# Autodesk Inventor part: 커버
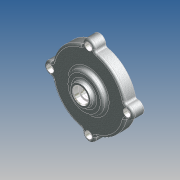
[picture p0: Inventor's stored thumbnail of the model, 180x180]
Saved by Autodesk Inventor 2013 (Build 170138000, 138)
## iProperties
Company: 한국ATC센터
Created: 2012-05
Part Number: 커버
Document SubType Name: 모델링
Designer: KYOUNG IL JANG
Mass: 196.657 g
Surface Area: 278.607 cm^2
Volume: 72.5671 cm^3
Density: 2.71 g/cm^3
Material: 알루미늄-6061
변환 표준: STEP AP214IS
파일 이름: C:\Users\SeoGD\Desktop\?쒗뿕\而ㅻ쾭-1.stp
전처리기: Build: 253, Release: 2010 SP1 - Date: Wed 07/29/2009
전송 단위: 밀리미터
불확실성: 0.01
Author: KYOUNG IL JANG
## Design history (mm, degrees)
sketch "스케치1"
  geometry: L1 (0, 0)-(0, 26); L2 (50, 0)-(50, 15); L3 (50, 15)-(25, 15); L4 (25, 15)-(25, 21); L5 (25, 21)-(15, 21); L6 (15, 21)-(13.66, 26); L7 (13.66, 26)-(10, 26); L8 (50, 0)-(45, 0); L9 (45, 0)-(45, 10); L10 (45, 10)-(14.5, 10); L11 (14.5, 10)-(13.266, 3); L12 (13.266, 3)-(11, 3); L13 (11, 3)-(11, 16); L14 (11, 16)-(7.5, 16); L15 (7.5, 16)-(7.5, 19); L16 (7.5, 19)-(10, 19); L17 (10, 19)-(10, 26)
  constraints: 34 end point, 10 parallel, 2 perpendicular, 2 point on line, 1 vertical
  dimensions: "d11" = 100 diameter of L2 L1; "d12" = 22 diameter of L13 L1; "d13" = 90 diameter of L9 L1; "d14" = 15 distance between parallel lines of L3 L8; "d15" = 10 distance between parallel lines of L8 L10; "d16" = 29 diameter of L10.end L1; "d17" = 100 deg angle of L11 L10; "d18" = 7 distance between parallel lines of L12 L10; "d19" = 13 distance between parallel lines of L14 L12; "d20" = 3 distance between parallel lines of L16 L14; "d21" = 15 diameter of L15 L1; "d22" = 20 diameter of L17 L1; "d23" = 30 diameter of L5.end L1; "d24" = 6 distance between parallel lines of L5 L3; "d25" = 50 diameter of L4 L1; "d26" = 105 deg angle of L5 L6; "d50" = 26 distance of L1.start L1.end
revolve "회전1" sketch "스케치1" stored, may be unused: angle "d27" = 90 deg
sketch "스케치2" dims "d29" = 104
  geometry: A1 r 8.5 centre (0, 52) between (8.074, 49.344) and (-8.074, 49.344); A2 r 50 centre (0, 0) between (-8.074, 49.344) and (8.074, 49.344) reference; 2 further points
  constraints: 4 point on circle, 2 vertical alignment, 1 centre point, 1 coincident, 2 other
  dimensions: "d28" = 17 diameter of A1
extrude "돌출1" join sketch "스케치2" stored distance "d30" = 10; taper "d31" = 0 deg
fillet "모깎기3" dims "d32" = 3
fillet "모깎기4" dims "d45" = 3, "d46" = 0.2
chamfer "모따기1" distance "d47" = 1; stored, may be unused: second distance "d48" = 2, angle "d49" = 45 deg
hole "구멍2" diameter "d38" = 5.5; stored, may be unused: countersink angle "d42" = 90 deg, drill point angle "d44" = 118 deg; dims "d36" = 10, "d37" = 10, "d39" = 6, "d40" = 9.5, "d41" = 5.4, "d43" = 8
node "솔리드1"
node "솔리드 본체"
node "곡면 본체"
pattern_circular "원형 패턴1" dims angle "d34" = 360 deg
pattern_circular "원형 패턴2" dims angle "d52" = 360 deg
node "솔리드2"
